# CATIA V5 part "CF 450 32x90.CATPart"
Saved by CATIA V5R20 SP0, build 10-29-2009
Part number: CF 450 32x90
Definition: NONE
Nomenclature: CF 450 32x90
Source: Unknown
Description: CF 450 32x90
Bounding box of the stored display mesh (mm): x -26.5 to 26.5, y 0 to 90, z -26.5 to 26.5
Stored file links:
  C:\Users\Utente\Desktop\IO LAVORO\3D X SITO CF\X SITO\CF 450\CF 450 32x90.CATPart
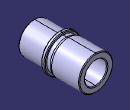
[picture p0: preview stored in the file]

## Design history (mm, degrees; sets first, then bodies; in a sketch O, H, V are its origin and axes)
Body1 "CF 450 32x90" (main body)
  Solid1: solid without history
